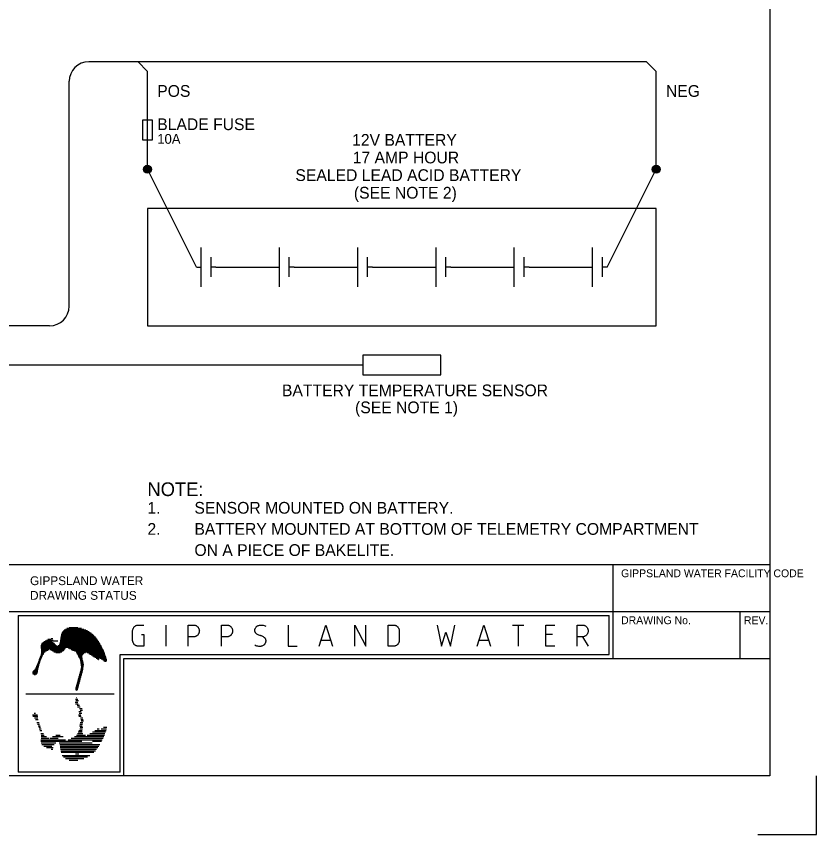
# Model space of a CAD drawing. Extents: x 0 to 841, y 0 to 594.
# Drawn here: x 636.5 to 841, y 0 to 209.1 of the extents above; entities that cross this region are included whole.
import ezdxf

# ---------------------------------------------------------------- set-up
doc = ezdxf.new("R2010")
doc.units = 0
for name, color, linetype in [('A1BORDER', 7, 'Continuous'), ('Level 1', 7, 'Continuous'), ('Level 10', 7, 'Continuous')]:
    doc.layers.add(name, color=color, linetype=linetype)

msp = doc.modelspace()

# ---------------------------------------------------------------- linework, layer by layer
at = {"layer": 'A1BORDER'}
for p, q in [((829, 581), (829, 15)), ((592.5, 69), (829, 69)), ((789, 45), (789, 69)), ((28, 57), (829, 57)), ((821.5, 45), (821.5, 57)), ((637, 56), (788, 56)), ((637, 56), (637, 16)), ((788, 46), (788, 56)), ((648.74, 52.32), (654.24, 52.32)), ((649.02, 52.52), (653.76, 52.52)), ((649.39, 52.72), (653.15, 52.72)), ((650.01, 52.92), (652.2, 52.92)), ((647.81, 50.32), (656.86, 50.32)), ((647.85, 50.52), (656.69, 50.52)), ((647.88, 50.72), (656.5, 50.72)), ((647.91, 50.92), (656.3, 50.92)), ((647.96, 51.12), (656.08, 51.12)), ((648.03, 51.32), (655.85, 51.32)), ((648.12, 51.52), (655.59, 51.52)), ((648.23, 51.72), (655.31, 51.72)), ((648.37, 51.92), (655, 51.92)), ((648.53, 52.12), (654.64, 52.12)), ((642.73, 48.12), (658.25, 48.12)), ((642.75, 48.32), (646.79, 48.32)), ((642.81, 48.52), (646.55, 48.52)), ((642.9, 48.72), (646.37, 48.72)), ((643.04, 48.92), (646.16, 48.92)), ((643.26, 49.12), (645.9, 49.12)), ((643.54, 49.32), (645.57, 49.32)), ((643.85, 49.52), (647.09, 49.52)), ((644.18, 49.72), (645.89, 49.72)), ((644.54, 49.92), (645.36, 49.92)), ((645.37, 50.12), (645.86, 50.12)), ((647.19, 48.32), (658.14, 48.32)), ((647.42, 48.52), (658.03, 48.52)), ((647.54, 48.72), (657.92, 48.72)), ((647.61, 48.92), (657.8, 48.92)), ((647.63, 49.12), (657.68, 49.12)), ((647.66, 49.32), (657.57, 49.32)), ((647.69, 49.52), (657.44, 49.52)), ((647.71, 49.72), (657.31, 49.72)), ((647.75, 49.92), (657.17, 49.92)), ((647.78, 50.12), (657.02, 50.12)), ((642.74, 47.92), (658.35, 47.92)), ((642.79, 47.72), (649.08, 47.72)), ((642.79, 46.12), (643.4, 46.12)), ((642.83, 47.52), (648.95, 47.52)), ((642.84, 46.32), (643.5, 46.32)), ((642.85, 47.31), (644.88, 47.31)), ((642.87, 47.12), (644.57, 47.12)), ((642.87, 46.52), (643.6, 46.52)), ((642.88, 46.92), (644.23, 46.92)), ((642.88, 46.72), (643.83, 46.72)), ((645.14, 47.31), (648.83, 47.31)), ((645.49, 47.12), (648.67, 47.12)), ((645.76, 46.92), (648.42, 46.92)), ((646.05, 46.72), (648.11, 46.72)), ((646.62, 46.52), (647.67, 46.52)), ((649.72, 47.72), (658.45, 47.72)), ((650.12, 47.52), (658.55, 47.52)), ((650.48, 47.31), (658.64, 47.31)), ((650.87, 47.12), (658.73, 47.12)), ((651.36, 46.92), (658.82, 46.92)), ((651.76, 46.72), (658.9, 46.72)), ((651.88, 46.52), (654.15, 46.52)), ((651.99, 46.32), (653.71, 46.32)), ((652.1, 46.12), (653.52, 46.12)), ((654.57, 46.52), (658.99, 46.52)), ((655, 46.32), (659.07, 46.32)), ((655.31, 46.12), (659.14, 46.12)), ((663, 46), (788, 46)), ((663, 16), (663, 46)), ((641.99, 43.92), (642.48, 43.92)), ((642.06, 44.12), (642.55, 44.12)), ((642.13, 44.32), (642.62, 44.32)), ((642.21, 44.52), (642.69, 44.52)), ((642.28, 44.72), (642.76, 44.72)), ((642.35, 44.92), (642.83, 44.92)), ((642.43, 45.12), (642.9, 45.12)), ((642.5, 45.32), (643, 45.32)), ((642.57, 45.52), (643.1, 45.52)), ((642.65, 45.72), (643.2, 45.72)), ((642.72, 45.92), (643.3, 45.92)), ((652.2, 45.92), (653.4, 45.92)), ((652.31, 45.72), (653.33, 45.72)), ((652.41, 45.52), (653.31, 45.52)), ((652.5, 45.32), (653.34, 45.32)), ((652.6, 45.12), (653.38, 45.12)), ((652.69, 44.92), (653.41, 44.92)), ((652.78, 44.72), (653.44, 44.72)), ((652.83, 44.52), (653.48, 44.52)), ((652.86, 44.32), (653.53, 44.32)), ((652.89, 44.12), (653.57, 44.12)), ((652.91, 43.92), (653.62, 43.92)), ((655.62, 45.92), (659.22, 45.92)), ((655.93, 45.72), (659.29, 45.72)), ((656.24, 45.52), (659.35, 45.52)), ((656.55, 45.32), (659.42, 45.32)), ((656.86, 45.12), (657.74, 45.12)), ((657.17, 44.92), (657.68, 44.92)), ((657.51, 44.72), (657.54, 44.72)), ((657.91, 45.12), (659.48, 45.12)), ((658.19, 44.92), (659.54, 44.92)), ((658.47, 44.72), (659.59, 44.72)), ((658.75, 44.52), (659.58, 44.52)), ((659.02, 44.32), (659.47, 44.32)), ((664, 45), (829, 45)), ((664, 15), (664, 45)), ((640.9, 41.92), (641.97, 41.92)), ((641.1, 42.12), (642, 42.12)), ((641.25, 42.31), (642.04, 42.31)), ((641.37, 42.52), (642.09, 42.52)), ((641.46, 42.72), (642.15, 42.72)), ((641.55, 42.92), (642.2, 42.92)), ((641.64, 43.12), (642.25, 43.12)), ((641.73, 43.32), (642.3, 43.32)), ((641.82, 43.51), (642.35, 43.51)), ((641.91, 43.72), (642.41, 43.72)), ((652.85, 41.92), (653.45, 41.92)), ((652.9, 42.12), (653.49, 42.12)), ((652.94, 43.72), (653.67, 43.72)), ((652.95, 42.31), (653.53, 42.31)), ((652.97, 43.51), (653.71, 43.51)), ((652.99, 42.52), (653.57, 42.52)), ((653, 43.32), (653.69, 43.32)), ((653.02, 43.12), (653.67, 43.12)), ((653.03, 42.72), (653.61, 42.72)), ((653.05, 42.92), (653.64, 42.92)), ((640.62, 41.32), (641.88, 41.32)), ((640.63, 41.52), (641.93, 41.52)), ((640.72, 41.12), (641.73, 41.12)), ((640.73, 41.72), (641.95, 41.72)), ((641.03, 40.92), (641.43, 40.92)), ((652.3, 39.92), (652.93, 39.92)), ((652.36, 40.12), (652.99, 40.12)), ((652.41, 40.32), (653.04, 40.32)), ((652.47, 40.52), (653.1, 40.52)), ((652.52, 40.72), (653.15, 40.72)), ((652.57, 40.92), (653.2, 40.92)), ((652.63, 41.12), (653.26, 41.12)), ((652.68, 41.32), (653.31, 41.32)), ((652.74, 41.52), (653.37, 41.52)), ((652.79, 41.72), (653.41, 41.72)), ((651.71, 37.72), (652.34, 37.72)), ((651.76, 37.92), (652.39, 37.92)), ((651.82, 38.12), (652.44, 38.12)), ((651.87, 38.32), (652.5, 38.32)), ((651.92, 38.52), (652.55, 38.52)), ((651.98, 38.72), (652.61, 38.72)), ((652.03, 38.92), (652.66, 38.92)), ((652.09, 39.12), (652.72, 39.12)), ((652.14, 39.32), (652.77, 39.32)), ((652.2, 39.52), (652.82, 39.52)), ((652.25, 39.72), (652.88, 39.72)), ((638.93, 35.98), (661.47, 35.98)), ((651.63, 37.32), (652.23, 37.32)), ((651.64, 37.12), (652.17, 37.12)), ((651.65, 37.52), (652.28, 37.52)), ((651.79, 36.92), (651.9, 36.92)), ((651.54, 33.84), (652.17, 33.84)), ((651.63, 34.64), (652.23, 34.64)), ((651.71, 34.24), (652.34, 34.24)), ((651.79, 35.04), (651.9, 35.04)), ((651.65, 33.44), (652.28, 33.44)), ((652.03, 33.04), (652.66, 33.04)), ((652.14, 32.64), (652.77, 32.64)), ((652.47, 31.44), (653.1, 31.44)), ((652.66, 32.24), (653.29, 32.24)), ((652.77, 31.84), (653.4, 31.84)), ((640.62, 30.64), (641.88, 30.64)), ((640.73, 30.24), (641.95, 30.24)), ((641.03, 31.04), (641.43, 31.04)), ((641.1, 29.84), (642, 29.84)), ((641.37, 29.44), (642.09, 29.44)), ((652.34, 30.64), (652.97, 30.64)), ((652.45, 30.24), (653.07, 30.24)), ((652.57, 31.04), (653.2, 31.04)), ((652.9, 29.84), (653.49, 29.84)), ((652.99, 29.44), (653.57, 29.44)), ((641.73, 28.64), (642.3, 28.64)), ((641.91, 28.24), (642.41, 28.24)), ((642.06, 27.84), (642.55, 27.84)), ((642.21, 27.44), (642.69, 27.44)), ((652.66, 27.84), (653.35, 27.84)), ((652.72, 28.24), (653.44, 28.24)), ((652.77, 28.64), (653.46, 28.64)), ((652.83, 27.44), (653.48, 27.44)), ((653.05, 29.04), (653.64, 29.04)), ((658.75, 27.44), (659.58, 27.44)), ((642.35, 27.04), (642.83, 27.04)), ((642.5, 26.64), (643, 26.64)), ((642.79, 25.84), (643.4, 25.84)), ((642.87, 25.44), (643.6, 25.44)), ((646.62, 25.44), (647.67, 25.44)), ((651.88, 25.44), (654.15, 25.44)), ((652.1, 25.84), (653.52, 25.84)), ((652.31, 26.24), (653.33, 26.24)), ((652.5, 26.64), (653.34, 26.64)), ((652.69, 27.04), (653.41, 27.04)), ((654.57, 25.44), (658.99, 25.44)), ((655.31, 25.84), (659.14, 25.84)), ((655.93, 26.24), (659.29, 26.24)), ((656.55, 26.64), (659.42, 26.64)), ((657.17, 27.04), (657.68, 27.04)), ((658.19, 27.04), (659.54, 27.04)), ((642.73, 23.84), (653.27, 23.84)), ((642.79, 24.24), (649.08, 24.24)), ((642.81, 23.44), (646.55, 23.44)), ((642.85, 24.65), (644.88, 24.65)), ((642.88, 25.04), (644.23, 25.04)), ((643.04, 23.04), (646.16, 23.04)), ((645.14, 24.65), (647.18, 24.65)), ((645.76, 25.04), (648.42, 25.04)), ((647.42, 23.44), (655.89, 23.44)), ((647.61, 23.04), (657.8, 23.04)), ((649.72, 24.24), (658.45, 24.24)), ((650.48, 24.65), (658.64, 24.65)), ((651.36, 25.04), (658.82, 25.04)), ((655.94, 23.84), (658.25, 23.84)), ((643.54, 22.64), (645.57, 22.64)), ((644.18, 22.24), (645.89, 22.24)), ((645.37, 21.84), (645.86, 21.84)), ((647.66, 22.64), (657.57, 22.64)), ((647.71, 22.24), (657.31, 22.24)), ((647.78, 21.84), (657.02, 21.84)), ((647.85, 21.44), (656.69, 21.44)), ((647.91, 21.04), (656.3, 21.04)), ((648.23, 20.24), (655.31, 20.24)), ((648.53, 19.84), (654.64, 19.84)), ((649.02, 19.44), (653.76, 19.44)), ((650.01, 19.04), (652.2, 19.04)), ((651.57, 20.64), (652.44, 20.64)), ((829, 15), (28, 15)), ((663, 16), (637, 16)), ((829, 15), (829, 15)), ((841, 0), (841, 15)), ((826, 0), (841, 0))]:
    msp.add_line(p, q, dxfattribs=at)
for points in [[(668.49, 51.15), (669.06, 51.15), (669.06, 48.16), (667.64, 48.16), (667.51, 48.16), (667.39, 48.18), (667.28, 48.21), (667.15, 48.25), (667.04, 48.3), (666.93, 48.36), (666.82, 48.43), (666.73, 48.51), (666.64, 48.6), (666.55, 48.7), (666.48, 48.8), (666.41, 48.91), (666.35, 49.02), (666.31, 49.14), (666.27, 49.27), (666.24, 49.39), (666.22, 49.52), (666.22, 49.66), (666.22, 52.05), (666.22, 52.18), (666.24, 52.31), (666.27, 52.43), (666.31, 52.56), (666.35, 52.67), (666.41, 52.79), (666.48, 52.9), (666.55, 53), (666.64, 53.1), (666.73, 53.19), (666.82, 53.27), (666.93, 53.34), (667.04, 53.4), (667.15, 53.45), (667.28, 53.49), (667.39, 53.52), (667.51, 53.54), (667.64, 53.54), (669.06, 53.54)], [(674.74, 48.16), (674.74, 53.54)], [(680.42, 48.16), (680.42, 53.54), (681.84, 53.54), (681.96, 53.54), (682.08, 53.52), (682.2, 53.49), (682.32, 53.45), (682.43, 53.4), (682.54, 53.34), (682.65, 53.27), (682.74, 53.19), (682.84, 53.1), (682.92, 53), (682.99, 52.9), (683.06, 52.79), (683.12, 52.67), (683.17, 52.56), (683.21, 52.43), (683.23, 52.31), (683.25, 52.18), (683.26, 52.05), (683.25, 51.91), (683.23, 51.78), (683.21, 51.66), (683.17, 51.53), (683.12, 51.42), (683.06, 51.3), (682.99, 51.19), (682.92, 51.09), (682.84, 50.99), (682.74, 50.9), (682.65, 50.82), (682.54, 50.75), (682.43, 50.69), (682.32, 50.64), (682.2, 50.6), (682.08, 50.57), (681.96, 50.55), (681.84, 50.55), (680.42, 50.55)], [(688.93, 48.16), (688.93, 53.54), (690.35, 53.54), (690.47, 53.54), (690.59, 53.52), (690.71, 53.49), (690.83, 53.45), (690.94, 53.4), (691.05, 53.34), (691.16, 53.27), (691.26, 53.19), (691.35, 53.1), (691.43, 53), (691.51, 52.9), (691.57, 52.79), (691.63, 52.67), (691.68, 52.56), (691.72, 52.43), (691.75, 52.31), (691.76, 52.18), (691.77, 52.05), (691.76, 51.91), (691.75, 51.78), (691.72, 51.66), (691.68, 51.53), (691.63, 51.42), (691.57, 51.3), (691.51, 51.19), (691.43, 51.09), (691.35, 50.99), (691.26, 50.9), (691.16, 50.82), (691.05, 50.75), (690.94, 50.69), (690.83, 50.64), (690.71, 50.6), (690.59, 50.57), (690.47, 50.55), (690.35, 50.55), (688.93, 50.55)], [(697.45, 48.46), (697.67, 48.36), (697.9, 48.27), (698.12, 48.21), (698.36, 48.17), (698.6, 48.16), (698.84, 48.16), (698.87, 48.16), (699.03, 48.18), (699.18, 48.21), (699.33, 48.26), (699.48, 48.32), (699.62, 48.4), (699.72, 48.46), (699.81, 48.53), (699.9, 48.61), (699.98, 48.69), (700.05, 48.78), (700.11, 48.88), (700.17, 48.99), (700.22, 49.09), (700.25, 49.21), (700.28, 49.32), (700.29, 49.36), (700.3, 49.44), (700.3, 49.52), (700.3, 49.61), (700.29, 49.69), (700.27, 49.77), (700.25, 49.86), (700.22, 49.93), (700.18, 50.01), (700.14, 50.09), (700.09, 50.15), (700.04, 50.21), (700.01, 50.25), (699.85, 50.39), (699.69, 50.51), (699.52, 50.61), (699.34, 50.7), (699.15, 50.78), (698.95, 50.83), (698.87, 50.85), (698.68, 50.9), (698.49, 50.96), (698.3, 51.04), (698.12, 51.14), (697.96, 51.26), (697.8, 51.39), (697.73, 51.45), (697.67, 51.51), (697.62, 51.57), (697.58, 51.64), (697.53, 51.71), (697.5, 51.79), (697.47, 51.87), (697.46, 51.95), (697.44, 52.04), (697.43, 52.12), (697.43, 52.21), (697.44, 52.29), (697.45, 52.35), (697.47, 52.46), (697.51, 52.58), (697.55, 52.69), (697.61, 52.79), (697.67, 52.89), (697.74, 52.99), (697.82, 53.07), (697.9, 53.15), (697.99, 53.23), (698.02, 53.24), (698.15, 53.33), (698.3, 53.4), (698.44, 53.45), (698.6, 53.5), (698.75, 53.52), (698.87, 53.54), (699.11, 53.55), (699.35, 53.53), (699.58, 53.49), (699.82, 53.43), (700.04, 53.35), (700.27, 53.25)], [(705.96, 53.54), (705.96, 48.16), (708.23, 48.16)], [(713.91, 48.16), (715.61, 53.54), (717.32, 48.16)], [(722.99, 48.16), (722.99, 53.54), (725.83, 48.16), (725.83, 53.54)], [(731.52, 48.16), (731.52, 53.54), (732.94, 53.54), (733.06, 53.54), (733.18, 53.52), (733.3, 53.49), (733.42, 53.45), (733.53, 53.4), (733.64, 53.34), (733.75, 53.27), (733.84, 53.19), (733.94, 53.1), (734.02, 53), (734.09, 52.9), (734.16, 52.79), (734.22, 52.67), (734.27, 52.56), (734.31, 52.43), (734.33, 52.31), (734.35, 52.18), (734.36, 52.05), (734.36, 49.66), (734.35, 49.52), (734.33, 49.39), (734.31, 49.27), (734.27, 49.14), (734.22, 49.02), (734.16, 48.91), (734.09, 48.8), (734.02, 48.7), (733.94, 48.6), (733.84, 48.51), (733.75, 48.43), (733.64, 48.36), (733.53, 48.3), (733.42, 48.25), (733.3, 48.21), (733.18, 48.18), (733.06, 48.16), (732.94, 48.16), (731.52, 48.16)], [(744.01, 53.54), (745.14, 48.16), (746.28, 51.75), (747.41, 48.16), (748.55, 53.54)], [(754.22, 48.16), (755.92, 53.54), (757.63, 48.16)], [(763.31, 53.54), (766.15, 53.54)], [(764.73, 53.54), (764.73, 48.16)], [(774.09, 48.16), (771.82, 48.16), (771.82, 53.54), (774.09, 53.54)], [(779.78, 48.16), (779.78, 53.54), (781.2, 53.54), (781.32, 53.54), (781.44, 53.52), (781.56, 53.49), (781.68, 53.45), (781.79, 53.4), (781.9, 53.34), (782.01, 53.27), (782.1, 53.19), (782.2, 53.1), (782.28, 53), (782.35, 52.9), (782.42, 52.79), (782.48, 52.67), (782.53, 52.56), (782.56, 52.43), (782.59, 52.31), (782.61, 52.18), (782.61, 52.05), (782.61, 51.91), (782.59, 51.78), (782.56, 51.66), (782.53, 51.53), (782.48, 51.42), (782.42, 51.3), (782.35, 51.19), (782.28, 51.09), (782.2, 50.99), (782.1, 50.9), (782.01, 50.82), (781.9, 50.75), (781.79, 50.69), (781.68, 50.64), (781.56, 50.6), (781.44, 50.57), (781.32, 50.55), (781.2, 50.55), (779.78, 50.55)], [(773.53, 51.15), (771.82, 51.15)], [(781.2, 50.55), (782.61, 48.16)], [(714.48, 49.66), (716.75, 49.66)], [(754.79, 49.66), (757.06, 49.66)]]:
    msp.add_lwpolyline(points, dxfattribs=at)
at = {"layer": 'Level 1'}
for p, q in [((797.5, 197.47), (655, 197.47)), ((670, 195), (667.5, 197.5)), ((797.5, 197.47), (800, 194.97)), ((670, 170), (670, 195)), ((800, 170), (800, 195)), ((650, 135), (650, 192.47)), ((682.5, 145), (670, 170)), ((787.5, 145), (800, 170)), ((687.5, 145), (702.5, 145)), ((707.5, 145), (722.5, 145)), ((727.5, 145), (742.5, 145)), ((747.5, 145), (762.5, 145)), ((767.5, 145), (782.5, 145)), ((645, 130), (255, 130)), ((245, 120), (725, 120))]:
    msp.add_line(p, q, dxfattribs=at)
for points in [[(800, 130), (800, 160), (670, 160), (670, 130)], [(725, 117.5), (745, 117.5), (745, 122.5), (725, 122.5)]]:
    msp.add_lwpolyline(points, close=True, dxfattribs=at)
for centre, start, end in [((655, 192.47), 90, 180), ((645, 135), 270, 0)]:
    msp.add_arc(centre, 5, start, end, dxfattribs=at)
at = {"layer": 'Level 10'}
for p, q in [((669, 170), (669, 170)), ((669.3, 169.29), (669.3, 170.71)), ((669.6, 169.08), (669.6, 170.92)), ((669.9, 169.01), (669.9, 170.99)), ((670.2, 169.02), (670.2, 170.98)), ((670.5, 169.13), (670.5, 170.87)), ((670.8, 169.4), (670.8, 170.6)), ((799, 170), (799, 170)), ((799.3, 169.29), (799.3, 170.71)), ((799.6, 169.08), (799.6, 170.92)), ((799.9, 169.01), (799.9, 170.99)), ((800.2, 169.02), (800.2, 170.98)), ((800.5, 169.13), (800.5, 170.87)), ((800.8, 169.4), (800.8, 170.6)), ((683.74, 140), (683.74, 150)), ((703.74, 140), (703.74, 150)), ((723.74, 140), (723.74, 150)), ((743.74, 140), (743.74, 150)), ((763.74, 140), (763.74, 150)), ((783.74, 140), (783.74, 150)), ((686.24, 142.5), (686.24, 147.5)), ((706.24, 142.5), (706.24, 147.5)), ((726.24, 142.5), (726.24, 147.5)), ((746.24, 142.5), (746.24, 147.5)), ((766.24, 142.5), (766.24, 147.5)), ((786.24, 142.5), (786.24, 147.5)), ((682.5, 145), (683.74, 145)), ((687.5, 145), (686.24, 145)), ((702.5, 145), (703.74, 145)), ((707.5, 145), (706.24, 145)), ((722.5, 145), (723.74, 145)), ((727.5, 145), (726.24, 145)), ((742.5, 145), (743.74, 145)), ((747.5, 145), (746.24, 145)), ((762.5, 145), (763.74, 145)), ((767.5, 145), (766.24, 145)), ((782.5, 145), (783.74, 145)), ((787.5, 145), (786.24, 145))]:
    msp.add_line(p, q, dxfattribs=at)
msp.add_lwpolyline([(670, 177.5), (671.25, 177.5), (671.25, 182.5), (668.75, 182.5), (668.75, 177.5), (670, 177.5)], dxfattribs=at)
for centre in [(670, 170), (800, 170)]:
    msp.add_circle(centre, 1, dxfattribs=at)

# ---------------------------------------------------------------- texts
at = {"layer": 'A1BORDER'}
for s, height, p in [('GIPPSLAND WATER FACILITY CODE', 2, (791.03, 65.77)), ('GIPPSLAND WATER', 2.25, (640, 63.75)), ('DRAWING STATUS', 2.25, (640, 60)), ('DRAWING No.', 2, (791.03, 53.77)), ('REV.', 2, (822.43, 53.77))]:
    msp.add_text(s, height=height, dxfattribs=at).set_placement(p)
at = {"layer": 'Level 1'}
for s, height, p in [('POS', 3, (672.5, 188.5)), ('NEG', 3, (802.5, 188.5)), ('BLADE FUSE', 3, (672.5, 180)), ('10A', 2.5, (672.5, 176.5)), ('12V BATTERY', 3, (722.3, 176)), ('17 AMP HOUR', 3, (722.45, 171.5)), ('SEALED LEAD ACID BATTERY', 3, (707.81, 167)), ('(SEE NOTE 2)', 3, (722.75, 162.5)), ('BATTERY TEMPERATURE SENSOR', 3, (704.37, 112)), ('(SEE NOTE 1)', 3, (723.05, 107.66)), ('NOTE:', 3.5, (670, 86.5)), ('1.', 3, (670, 82)), ('SENSOR MOUNTED ON BATTERY.', 3, (682, 82)), ('2.', 3, (670, 76.6)), ('BATTERY MOUNTED AT BOTTOM OF TELEMETRY COMPARTMENT', 3, (682, 76.6)), ('ON A PIECE OF BAKELITE.', 3, (682, 71.2))]:
    msp.add_text(s, height=height, dxfattribs=at).set_placement(p)

doc.saveas('drawing.dxf')
